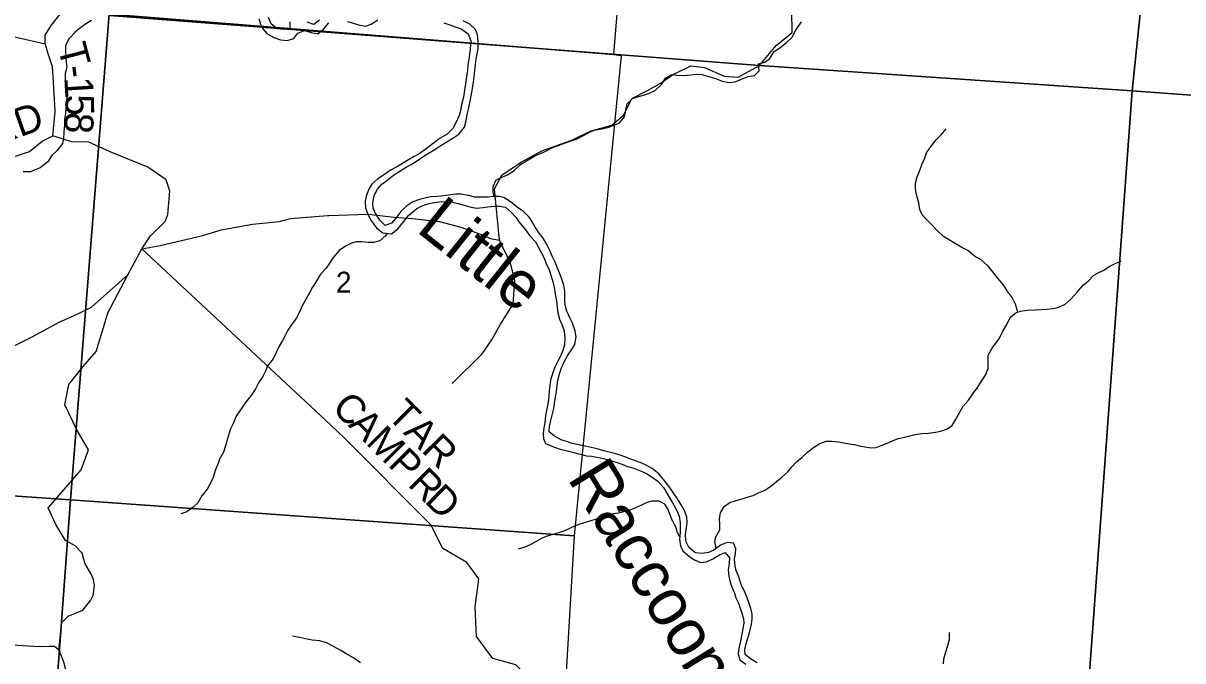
# Model space of a CAD drawing. Extents: x 1715311 to 2083412, y 146837 to 553079.
# Drawn here: x 1975223 to 1987413, y 370994 to 377700 of the extents above; entities that cross this region are included whole.
import ezdxf

# ---------------------------------------------------------------- set-up
doc = ezdxf.new("R2010")
doc.units = 0
for name, color, linetype in [('GM_X_Adjacent_County', 7, 'Continuous'), ('GM_X_County', 7, 'Continuous'), ('GM_X_County_Road', 7, 'Continuous'), ('GM_X_Major_River', 7, 'Continuous'), ('GM_X_Major_River_Text', 7, 'Continuous'), ('GM_X_Minor_River', 7, 'Continuous'), ('GM_X_Section', 7, 'Continuous'), ('GM_X_Section_Text', 7, 'Continuous'), ('GM_X_Township', 7, 'Continuous'), ('GM_X_Township_Road', 7, 'Continuous'), ('GM_X_Township_Road_Text', 7, 'Continuous'), ('GM_X_Township_ROW', 7, 'Continuous')]:
    doc.layers.add(name, color=color, linetype=linetype)

msp = doc.modelspace()

# ---------------------------------------------------------------- linework, layer by layer
at = {"layer": 'GM_X_Adjacent_County'}
for points in [[(2002882, 375803), (1999924, 376023), (1996643, 376255), (1995226, 376368), (1992658, 376556), (1989295, 376815), (1988220, 376891), (1986880, 376990), (1987114, 379254)], [(1983804, 337792), (1984007, 340156), (1984423, 345015), (1984436, 345173), (1984507, 346000), (1984847, 350030), (1985384, 356640), (1985738, 360944), (1985956, 364228), (1986124, 366354), (1986156, 366752), (1986186, 367140), (1986209, 367496), (1986415, 370630), (1986880, 376990), (1988220, 376891), (1989295, 376815), (1992658, 376556), (1995226, 376368), (1996643, 376255), (1999924, 376023), (2002882, 375803)]]:
    msp.add_lwpolyline(points, dxfattribs=at)
at = {"layer": 'GM_X_County'}
msp.add_lwpolyline([(1987114, 379254), (1986880, 376990), (1986415, 370630), (1986209, 367496), (1986186, 367140), (1986156, 366752), (1986124, 366354), (1985956, 364228), (1985738, 360944), (1985384, 356640), (1984847, 350030), (1984507, 346000), (1984436, 345173), (1984423, 345015), (1984007, 340156), (1983804, 337792)], dxfattribs=at)
at = {"layer": 'GM_X_County_Road'}
msp.add_lwpolyline([(1975056, 371165), (1975330, 371149), (1975407, 371145), (1975494, 371148), (1975553, 371148), (1975597, 371111), (1975645, 370985), (1975702, 370769), (1975789, 370518), (1975846, 370369), (1975879, 370297), (1975979, 370181), (1976450, 369883), (1976698, 369701), (1976832, 369573), (1976928, 369447), (1977044, 369244), (1977131, 369088), (1977161, 368912), (1977188, 368763), (1977746, 368276), (1977961, 367997)], dxfattribs=at)
at = {"layer": 'GM_X_Major_River'}
for points in [[(1977701, 377748), (1977718, 377690), (1977742, 377639), (1977787, 377587), (1977859, 377548), (1977929, 377524), (1977999, 377517), (1978067, 377539), (1978109, 377596), (1978180, 377624), (1978249, 377603), (1978321, 377588), (1978378, 377638), (1978434, 377702)], [(1978024, 377715), (1978026, 377641), (1977958, 377634), (1977894, 377642), (1977828, 377693), (1977803, 377761)], [(1978338, 377730), (1978278, 377687), (1978208, 377710)], [(1978630, 377716), (1978690, 377700), (1978762, 377679), (1978826, 377668), (1978888, 377692), (1978952, 377735)], [(1978994, 376008), (1979044, 376047), (1979115, 376101), (1979191, 376152), (1979247, 376184), (1979302, 376215), (1979368, 376257), (1979438, 376304), (1979491, 376338), (1979543, 376369), (1979603, 376405), (1979657, 376442), (1979740, 376492), (1979802, 376531), (1979861, 376605), (1979879, 376673), (1979890, 376741), (1979907, 376809), (1979921, 376879), (1979932, 376937), (1979942, 376993), (1979957, 377079), (1979963, 377135), (1979970, 377201), (1979978, 377267), (1979985, 377323), (1980006, 377434), (1980006, 377509), (1979999, 377577), (1979978, 377633), (1979918, 377689), (1979848, 377726)], [(1979646, 377704), (1979708, 377683), (1979764, 377663), (1979826, 377642), (1979901, 377589), (1979927, 377513), (1979922, 377425), (1979913, 377373), (1979907, 377319), (1979898, 377261), (1979892, 377207), (1979883, 377137), (1979871, 377061), (1979860, 376997), (1979850, 376921), (1979831, 376845), (1979818, 376779), (1979804, 376728), (1979769, 376652), (1979739, 376594), (1979680, 376534), (1979606, 376491), (1979535, 376437), (1979459, 376378), (1979393, 376331)], [(1979393, 376331), (1979332, 376297), (1979272, 376263), (1979210, 376224), (1979159, 376194), (1979085, 376153), (1979019, 376109), (1978950, 376064), (1978886, 376006), (1978857, 375955), (1978827, 375881), (1978816, 375829), (1978822, 375759), (1978849, 375680), (1978883, 375618), (1978938, 375546), (1979004, 375495), (1979095, 375486), (1979160, 375536), (1979223, 375615), (1979277, 375681), (1979360, 375752), (1979422, 375782), (1979490, 375803), (1979542, 375815), (1979598, 375822), (1979650, 375824), (1979720, 375821), (1979796, 375805), (1979932, 375764), (1979988, 375755), (1980058, 375761), (1980108, 375768), (1980178, 375774), (1980228, 375775), (1980294, 375765), (1980357, 375710), (1980401, 375660), (1980436, 375609), (1980502, 375527), (1980549, 375464), (1980609, 375400), (1980636, 375349), (1980670, 375283), (1980699, 375229), (1980725, 375162), (1980750, 375110), (1980774, 375038), (1980789, 374980), (1980803, 374922), (1980814, 374849), (1980829, 374779), (1980837, 374705), (1980844, 374655), (1980860, 374587), (1980885, 374531), (1980911, 374464), (1980918, 374386), (1980914, 374316), (1980897, 374256), (1980871, 374198), (1980844, 374147), (1980812, 374081), (1980785, 374011), (1980769, 373959), (1980758, 373897), (1980751, 373833), (1980747, 373779), (1980740, 373715), (1980728, 373643), (1980713, 373573), (1980705, 373497), (1980696, 373445), (1980688, 373381), (1980691, 373331), (1980713, 373279), (1980798, 373244), (1980866, 373221), (1980928, 373207), (1981010, 373184), (1981078, 373166), (1981144, 373151), (1981196, 373145), (1981254, 373136), (1981323, 373122), (1981385, 373105), (1981455, 373083), (1981517, 373062), (1981577, 373039), (1981643, 373019), (1981712, 372992), (1981774, 372964), (1981836, 372927), (1981895, 372885), (1981955, 372818), (1982049, 372655), (1982091, 372581), (1982118, 372515), (1982128, 372446), (1982129, 372392), (1982127, 372342)], [(1982361, 372122), (1982289, 372131), (1982223, 372181), (1982188, 372252), (1982185, 372322), (1982191, 372376), (1982202, 372446), (1982200, 372504), (1982175, 372574), (1982147, 372626), (1982100, 372699), (1982054, 372765), (1982009, 372830), (1981956, 372898), (1981904, 372961), (1981833, 373017), (1981765, 373056), (1981707, 373080), (1981627, 373109), (1981575, 373130), (1981510, 373152), (1981452, 373171), (1981382, 373189), (1981328, 373204), (1981256, 373222), (1981194, 373237), (1981131, 373253), (1981061, 373264), (1980995, 373280), (1980943, 373297), (1980879, 373319), (1980807, 373356), (1980752, 373403), (1980754, 373457), (1980769, 373523), (1980783, 373576), (1980800, 373648), (1980808, 373702), (1980819, 373766), (1980827, 373822), (1980836, 373892), (1980844, 373946), (1980865, 374022), (1980883, 374074), (1980906, 374130), (1980949, 374210), (1980987, 374263), (1981022, 374321), (1981036, 374401), (1981025, 374463), (1980997, 374544), (1980974, 374596), (1980936, 374670), (1980923, 374720), (1980917, 374771), (1980918, 374831), (1980916, 374881), (1980905, 374945), (1980889, 374997), (1980870, 375047), (1980848, 375105), (1980815, 375186), (1980783, 375250), (1980760, 375308), (1980728, 375371), (1980687, 375439), (1980647, 375491), (1980602, 375560), (1980572, 375610), (1980541, 375660), (1980483, 375719), (1980416, 375764), (1980350, 375816), (1980283, 375863), (1980231, 375877), (1980177, 375876), (1980103, 375870), (1980047, 375869), (1979969, 375871), (1979903, 375888), (1979823, 375901), (1979767, 375901), (1979717, 375895), (1979643, 375884), (1979577, 375877), (1979509, 375873), (1979459, 375862), (1979388, 375846), (1979320, 375821), (1979256, 375779), (1979193, 375720), (1979139, 375650), (1979096, 375598), (1979026, 375571), (1978973, 375629), (1978927, 375698), (1978902, 375756), (1978898, 375812), (1978913, 375886), (1978947, 375956), (1978994, 376008)], [(1982127, 372342), (1982122, 372274), (1982132, 372204), (1982157, 372152), (1982233, 372085), (1982286, 372053), (1982342, 372030), (1982406, 372036), (1982472, 372067), (1982541, 372109), (1982601, 372134), (1982647, 372076), (1982644, 372022), (1982635, 371950), (1982641, 371884), (1982656, 371821), (1982676, 371763), (1982699, 371707), (1982715, 371657), (1982741, 371599), (1982758, 371548), (1982778, 371494), (1982793, 371440), (1982797, 371390), (1982788, 371334), (1982776, 371274), (1982763, 371200), (1982747, 371126), (1982738, 371068), (1982756, 371004), (1982819, 370961)], [(1982937, 370972), (1982868, 371017), (1982812, 371061), (1982810, 371112), (1982823, 371177), (1982839, 371231), (1982858, 371289), (1982879, 371381), (1982885, 371433), (1982884, 371487), (1982870, 371543), (1982855, 371598), (1982833, 371656), (1982804, 371728), (1982778, 371780), (1982758, 371831), (1982737, 371895), (1982719, 371945), (1982706, 371995), (1982700, 372063), (1982709, 372119), (1982715, 372177), (1982688, 372232), (1982622, 372238), (1982554, 372211), (1982483, 372159), (1982427, 372132), (1982361, 372122)]]:
    msp.add_lwpolyline(points, dxfattribs=at)
at = {"layer": 'GM_X_Minor_River'}
for points in [[(1975941, 377727), (1975889, 377697), (1975829, 377655), (1975771, 377609), (1975707, 377539), (1975668, 377465), (1975666, 377413), (1975670, 377343), (1975676, 377289), (1975680, 377239), (1975665, 377169), (1975665, 377097), (1975681, 377021), (1975685, 376957), (1975677, 376881), (1975676, 376829), (1975666, 376753), (1975656, 376685), (1975656, 376627), (1975650, 376555), (1975645, 376485), (1975637, 376433), (1975575, 376359), (1975525, 376309), (1975477, 376237), (1975400, 376177), (1975350, 376157), (1975298, 376135), (1975222, 376136)], [(1980173, 375875), (1980163, 375925), (1980163, 375981), (1980195, 376051), (1980265, 376085), (1980319, 376107), (1980387, 376154), (1980452, 376212), (1980530, 376262), (1980600, 376304), (1980654, 376326), (1980724, 376358), (1980774, 376386), (1980848, 376413), (1980924, 376443), (1980978, 376461), (1981040, 376481), (1981114, 376519), (1981182, 376556), (1981238, 376580), (1981308, 376590), (1981380, 376608), (1981430, 376628), (1981486, 376648), (1981545, 376716), (1981559, 376784), (1981571, 376852), (1981627, 376909), (1981679, 376925), (1981745, 376943), (1981807, 376963), (1981865, 376993), (1981931, 377055), (1981978, 377125), (1982042, 377160), (1982094, 377152), (1982164, 377148), (1982240, 377158), (1982300, 377164), (1982361, 377160), (1982431, 377139), (1982501, 377117), (1982571, 377091), (1982643, 377075), (1982707, 377084), (1982773, 377110), (1982845, 377138), (1982911, 377148), (1982959, 377200), (1982953, 377274), (1983019, 377290), (1983070, 377330), (1983116, 377402), (1983178, 377441), (1983246, 377497), (1983306, 377553), (1983346, 377627), (1983403, 377713)], [(1985678, 374662), (1985654, 374744), (1985618, 374814), (1985566, 374884), (1985525, 374953), (1985463, 375021), (1985415, 375085), (1985365, 375145), (1985293, 375210), (1985222, 375250), (1985154, 375310), (1985090, 375340), (1985018, 375382), (1984966, 375413), (1984897, 375457), (1984829, 375521), (1984771, 375581), (1984721, 375632), (1984671, 375684), (1984648, 375740), (1984636, 375806), (1984624, 375860), (1984610, 375912), (1984604, 375964), (1984604, 376016), (1984621, 376084), (1984643, 376144), (1984673, 376222), (1984697, 376274), (1984719, 376336), (1984768, 376408), (1984820, 376474), (1984872, 376524), (1984924, 376590)], [(1979049, 375491), (1979032, 375462), (1978970, 375412), (1978904, 375392), (1978850, 375394), (1978778, 375401), (1978726, 375399), (1978674, 375385), (1978612, 375355), (1978544, 375309), (1978486, 375239), (1978448, 375187), (1978407, 375123), (1978349, 375060), (1978301, 374984), (1978265, 374924), (1978231, 374864), (1978198, 374800), (1978156, 374728), (1978124, 374654), (1978092, 374594), (1978046, 374536), (1978004, 374470), (1977977, 374416), (1977949, 374364), (1977915, 374302), (1977849, 374170), (1977792, 374096), (1977768, 374042), (1977740, 373986), (1977698, 373923), (1977660, 373847), (1977620, 373783), (1977561, 373711), (1977513, 373643), (1977463, 373567), (1977435, 373497), (1977403, 373433), (1977382, 373369), (1977368, 373317), (1977348, 373255), (1977328, 373187), (1977286, 373115), (1977268, 373061), (1977241, 372995), (1977219, 372923), (1977191, 372863), (1977155, 372801), (1977101, 372729), (1977058, 372655), (1977008, 372609), (1976944, 372562), (1976878, 372540)], [(1982508, 372178), (1982494, 372247), (1982504, 372299), (1982544, 372373), (1982544, 372427), (1982543, 372487), (1982553, 372549), (1982593, 372619), (1982651, 372659), (1982719, 372679), (1982771, 372695), (1982843, 372719), (1982895, 372734), (1982951, 372760), (1983019, 372790), (1983093, 372838), (1983145, 372882), (1983198, 372924), (1983260, 372982), (1983304, 373033), (1983350, 373087), (1983408, 373131), (1983470, 373191), (1983540, 373245), (1983590, 373277), (1983664, 373303), (1983728, 373306), (1983788, 373298), (1983850, 373288), (1983906, 373276), (1983960, 373268), (1984012, 373254), (1984070, 373243), (1984136, 373233), (1984188, 373239), (1984240, 373259), (1984296, 373281), (1984362, 373309), (1984422, 373333), (1984474, 373342), (1984528, 373358), (1984598, 373376), (1984664, 373384), (1984738, 373388), (1984812, 373399), (1984864, 373409), (1984930, 373429), (1984988, 373469), (1985022, 373527), (1985059, 373593), (1985105, 373671), (1985161, 373735), (1985201, 373797), (1985251, 373863), (1985297, 373935), (1985340, 374000), (1985366, 374068), (1985368, 374134), (1985368, 374209), (1985410, 374282), (1985447, 374334), (1985485, 374386), (1985519, 374462), (1985563, 374530), (1985599, 374604), (1985649, 374650), (1985702, 374672), (1985780, 374682), (1985861, 374686), (1985927, 374689), (1985983, 374691), (1986049, 374699), (1986101, 374711), (1986175, 374745), (1986236, 374799), (1986298, 374868), (1986366, 374944), (1986416, 374988), (1986474, 375046), (1986524, 375076), (1986574, 375098), (1986646, 375146), (1986708, 375175), (1986765, 375196)], [(1982124, 372298), (1982098, 372346), (1982085, 372396), (1982049, 372467), (1982027, 372519), (1981999, 372591), (1981969, 372641), (1981908, 372675), (1981830, 372673), (1981780, 372660), (1981724, 372632), (1981659, 372604), (1981601, 372578), (1981547, 372566), (1981479, 372548), (1981423, 372541), (1981297, 372499), (1981245, 372483), (1981191, 372465), (1981075, 372433), (1980995, 372400), (1980925, 372364), (1980851, 372340), (1980779, 372318), (1980715, 372302), (1980665, 372277), (1980607, 372245), (1980551, 372213), (1980495, 372189), (1980425, 372169)], [(1978768, 370975), (1978694, 371025), (1978624, 371063), (1978553, 371108), (1978483, 371144), (1978411, 371184), (1978341, 371204), (1978259, 371213), (1978189, 371227), (1978127, 371239), (1978055, 371255)], [(1984896, 370963), (1984902, 371015), (1984917, 371079), (1984941, 371155), (1984959, 371217), (1984961, 371293)]]:
    msp.add_lwpolyline(points, dxfattribs=at)
at = {"layer": 'GM_X_Section'}
for points in [[(1976415, 383117), (1981866, 382722), (1981427, 377369), (1976128, 377795), (1976006, 377809)], [(1976006, 377809), (1976128, 377795), (1975721, 372688), (1970470, 373048), (1970801, 378233)], [(1976128, 377795), (1981427, 377369), (1981507, 377361), (1981016, 372310), (1975721, 372688)], [(1975721, 372688), (1975319, 367267), (1969998, 367683), (1970470, 373048)], [(1975721, 372688), (1981016, 372310), (1980696, 366871), (1975319, 367267)]]:
    msp.add_lwpolyline(points, close=True, dxfattribs=at)
at = {"layer": 'GM_X_Township'}
for points in [[(1987114, 379254), (1986880, 376990), (1982964, 377254), (1976132, 377779)], [(1976132, 377779), (1982964, 377254), (1986880, 376990), (1986415, 370630), (1986209, 367496), (1986186, 367140), (1986156, 366752), (1986124, 366354), (1985956, 364228), (1985738, 360944), (1985384, 356640)]]:
    msp.add_lwpolyline(points, dxfattribs=at)
at = {"layer": 'GM_X_Township_Road'}
for points in [[(1975534, 376516), (1975559, 376776), (1975541, 377080), (1975531, 377242), (1975487, 377367), (1975453, 377482), (1975453, 377573), (1975517, 377675), (1975651, 377844), (1975660, 377854)], [(1971216, 375707), (1971286, 375728), (1971352, 375720), (1971878, 375900), (1971897, 375906), (1971978, 375923), (1972731, 376085), (1972754, 376090), (1972830, 376109), (1973578, 376295), (1973603, 376301), (1973680, 376304), (1974450, 376334), (1974468, 376335), (1974552, 376327), (1975063, 376279), (1975070, 376279), (1975161, 376308), (1975259, 376340), (1975290, 376351), (1975344, 376395), (1975423, 376460), (1975534, 376516)], [(1980747, 370705), (1980664, 370740), (1980501, 370859), (1980402, 370951), (1980159, 371020), (1979989, 371249), (1979974, 371560), (1980014, 371856), (1979885, 372030), (1979633, 372176), (1979508, 372424), (1978601, 373336), (1978453, 373475)]]:
    msp.add_lwpolyline(points, dxfattribs=at)
at = {"layer": 'GM_X_Township_ROW'}
for points in [[(1975049, 374268), (1975311, 374399), (1975600, 374557), (1975783, 374635), (1975941, 374714), (1976322, 375052), (1976470, 375328), (1976663, 375363), (1977110, 375467), (1977304, 375527), (1977632, 375586), (1977915, 375616), (1978034, 375646), (1978421, 375676), (1978436, 375676), (1978854, 375690), (1979122, 375661), (1979316, 375646), (1979599, 375616), (1979822, 375556), (1980031, 375482), (1980135, 375437), (1980231, 375418), (1980177, 375959), (1980255, 376102), (1980452, 376234), (1980674, 376359), (1980979, 376467), (1981194, 376569), (1981409, 376628), (1981535, 376736), (1981619, 376909), (1981786, 376993), (1981929, 377071), (1982049, 377155), (1982240, 377250), (1982384, 377232), (1982593, 377143), (1982737, 377131), (1982964, 377254), (1983137, 377466), (1983305, 377603), (1983287, 378733)], [(1971548, 377111), (1971535, 377131), (1972368, 377711), (1972655, 377678), (1972822, 377613), (1973085, 377547), (1973385, 377591), (1973655, 377701), (1973897, 377745), (1974182, 377745), (1974437, 377774), (1974584, 377701), (1974869, 377606), (1975150, 377553), (1975453, 377482)], [(1978453, 373475), (1976470, 375328), (1976561, 375462), (1976716, 375615), (1976743, 375687), (1976765, 375934), (1976727, 376051), (1976534, 376185), (1976138, 376346), (1975913, 376448), (1975731, 376453), (1975534, 376516)], [(1979733, 373909), (1980046, 374222), (1980150, 374371), (1980240, 374535), (1980374, 374744), (1980389, 374997), (1980344, 375176), (1980231, 375418)], [(1975597, 371111), (1975629, 371397), (1975697, 371465), (1975848, 371527), (1975932, 371634), (1975958, 371682), (1975972, 371785), (1975961, 371851), (1975933, 371912), (1975872, 372023), (1975841, 372125), (1975770, 372205), (1975668, 372258), (1975566, 372428), (1975486, 372603), (1975560, 372687), (1975696, 372845), (1975832, 373002), (1975908, 373213), (1975787, 373424), (1975659, 373688), (1975704, 373899), (1975848, 374087), (1975991, 374246), (1976066, 374500), (1976111, 374653), (1976322, 375052)]]:
    msp.add_lwpolyline(points, dxfattribs=at)

# ---------------------------------------------------------------- texts
at = {"layer": 'GM_X_Major_River_Text'}
for s, rotation, p in [('Little', 321.5092, (1979342, 375518)), ('Raccoon', 301.5102, (1980937, 372914))]:
    msp.add_text(s, height=500, rotation=rotation, dxfattribs=at).set_placement(p)
at = {"layer": 'GM_X_Section_Text'}
msp.add_text('2', height=221, rotation=0, dxfattribs=at).set_placement((1978510, 374865))
at = {"layer": 'GM_X_Township_Road_Text'}
for s, rotation, p in [('T', 284.7684, (1975583, 377449)), ('-', 277.4344, (1975638, 377242)), ('1', 273.4825, (1975654, 377127)), ('5', 271.3624, (1975665, 376947)), ('RD', 19.4122, (1974916, 376404)), ('8', 266.1374, (1975669, 376771)), ('C', 315, (1978455, 373642)), ('TAR', 315, (1979037, 373563)), ('A', 315, (1978630, 373468)), ('M', 315, (1978816, 373281)), ('P', 315, (1979047, 373051)), ('R', 315.0247, (1979255, 372842)), ('D', 315.3413, (1979431, 372667))]:
    msp.add_text(s, height=300, rotation=rotation, dxfattribs=at).set_placement(p)

doc.saveas('drawing.dxf')
